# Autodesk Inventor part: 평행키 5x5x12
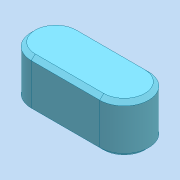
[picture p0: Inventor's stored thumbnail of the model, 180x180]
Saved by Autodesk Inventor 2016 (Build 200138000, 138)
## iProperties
Created: 2024-08
Part Number: 평행키 5x5x12
Material: 일반
Description: 키 및 해당 키홈
Document SubType Name: Modeling
Designer: pc-7
Density: 1 g/cm^3
Appearance: 기본값
Author: jhkim
Sending System: Autodesk Inventor 2025
Preprocessor: ST-DEVELOPER v20
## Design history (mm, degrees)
node "평행키 5x5x121"
node "솔리드1"
body "Solid1"
